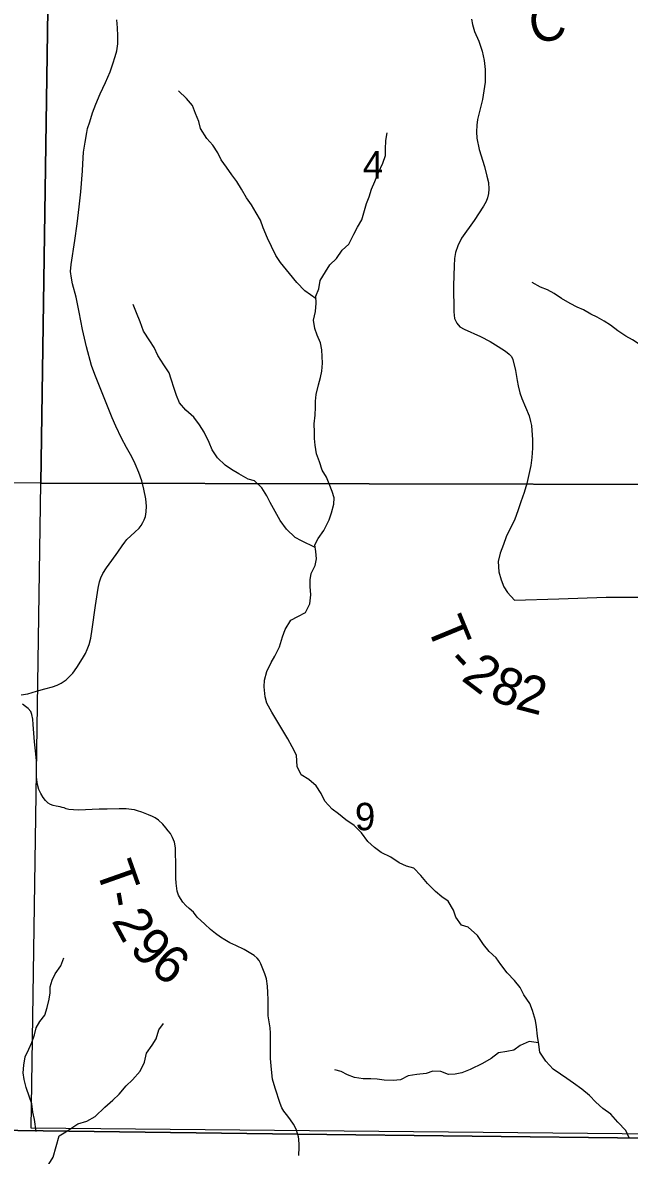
# Model space of a CAD drawing. Extents: x 0 to 34, y 0 to 22.
# Drawn here: x 6.729 to 7.655, y 16.596 to 18.326 of the extents above; entities that cross this region are included whole.
import ezdxf

# ---------------------------------------------------------------- set-up
doc = ezdxf.new("R2010")
doc.units = 0
for name, color, linetype in [('GM_X_County_Road', 7, 'Continuous'), ('GM_X_County_Road_Text', 7, 'Continuous'), ('GM_X_Minor_River', 7, 'Continuous'), ('GM_X_Rail_Line', 7, 'Continuous'), ('GM_X_Section', 7, 'Continuous'), ('GM_X_Section_Text', 7, 'Continuous'), ('GM_X_Township_Road', 7, 'Continuous'), ('GM_X_Township_Road_Text', 7, 'Continuous'), ('SH_Cut_Line', 7, 'Continuous')]:
    doc.layers.add(name, color=color, linetype=linetype)

msp = doc.modelspace()

# ---------------------------------------------------------------- linework, layer by layer
at = {"layer": 'GM_X_County_Road'}
msp.add_lwpolyline([(6.7266, 17.2991), (6.7365, 17.3011), (6.7502, 17.3047), (6.7629, 17.3083), (6.7745, 17.3115), (6.7815, 17.314), (6.7877, 17.3171), (6.7954, 17.3225), (6.7997, 17.3267), (6.8053, 17.3322), (6.8117, 17.3409), (6.8204, 17.3548), (6.8248, 17.3623), (6.8276, 17.3687), (6.8303, 17.3762), (6.8329, 17.3859), (6.835, 17.3998), (6.8402, 17.4358), (6.8442, 17.4625), (6.8462, 17.472), (6.848, 17.4782), (6.8511, 17.4846), (6.8569, 17.4934), (6.8649, 17.5043), (6.8741, 17.517), (6.8807, 17.5269), (6.8849, 17.5325), (6.8881, 17.5368), (6.9003, 17.548), (6.9067, 17.554), (6.9099, 17.5581), (6.9123, 17.5628), (6.9143, 17.5666), (6.9163, 17.5718), (6.9177, 17.5791), (6.918, 17.5874), (6.9167, 17.5989), (6.9138, 17.6136), (6.9108, 17.6261), (6.9063, 17.639), (6.9009, 17.6524), (6.8955, 17.663), (6.8875, 17.6772), (6.8798, 17.6913), (6.871, 17.7098), (6.8653, 17.7226), (6.8531, 17.7531), (6.8471, 17.7685), (6.8391, 17.7887), (6.8341, 17.8024), (6.8264, 17.8308), (6.8202, 17.8574), (6.8153, 17.8836), (6.8103, 17.9068), (6.8052, 17.9273), (6.8034, 17.9357), (6.8019, 17.9461), (6.803, 17.9568), (6.8085, 17.9934), (6.8122, 18.0185), (6.8151, 18.0448), (6.8178, 18.0678), (6.8204, 18.0999), (6.8206, 18.1104), (6.8218, 18.128), (6.8241, 18.1433), (6.8268, 18.1584), (6.828, 18.1645), (6.8312, 18.1744), (6.8356, 18.1883), (6.8404, 18.2016), (6.8472, 18.2171), (6.8555, 18.2348), (6.8623, 18.2509), (6.8666, 18.2632), (6.8701, 18.2741), (6.8725, 18.2828), (6.8742, 18.2939), (6.8741, 18.3057), (6.8735, 18.3182), (6.8728, 18.3303)], dxfattribs=at)
at = {"layer": 'GM_X_Minor_River'}
for points in [[(7.1769, 17.904), (7.1596, 17.9163), (7.1477, 17.9291), (7.1362, 17.943), (7.1228, 17.9597), (7.1156, 17.9706), (7.109, 17.9842), (7.1028, 17.9971), (7.0959, 18.0126), (7.092, 18.0243), (7.0855, 18.0356), (7.0782, 18.0477), (7.0705, 18.0587), (7.0629, 18.0719), (7.056, 18.0836), (7.0483, 18.0938), (7.0399, 18.1055), (7.0318, 18.1165), (7.0268, 18.1274), (7.0195, 18.1388), (7.0103, 18.149), (7.0004, 18.1644), (6.998, 18.175), (6.993, 18.1875), (6.9884, 18.1993), (6.9792, 18.2102), (6.967, 18.2219)], [(7.1753, 17.7267), (7.1763, 17.7385), (7.1763, 17.748), (7.1769, 17.7582), (7.1806, 17.7727), (7.1836, 17.7841), (7.1858, 17.7935), (7.1869, 17.8057), (7.1861, 17.8163), (7.1856, 17.8262), (7.1836, 17.8368), (7.1786, 17.8489), (7.1748, 17.8591), (7.1728, 17.8716), (7.1761, 17.8849), (7.1772, 17.8978), (7.1767, 17.9084), (7.1812, 17.9194), (7.1834, 17.932), (7.1913, 17.9453), (7.1977, 17.956), (7.2082, 17.9659), (7.2169, 17.9785), (7.2267, 17.9876), (7.2346, 18.0029), (7.2402, 18.0135), (7.2466, 18.0246), (7.2507, 18.039), (7.254, 18.05), (7.2581, 18.0599), (7.2618, 18.0717), (7.2667, 18.0835), (7.2723, 18.0972), (7.279, 18.1112), (7.2828, 18.123), (7.2827, 18.1329), (7.2837, 18.1462), (7.2856, 18.1579)], [(7.7613, 17.7616), (7.7464, 17.7741), (7.7353, 17.7869), (7.7215, 17.7997), (7.7074, 17.8098), (7.6967, 17.817), (7.6834, 17.826), (7.6704, 17.835), (7.6601, 17.8414), (7.6502, 17.8474), (7.638, 17.8553), (7.6266, 17.8639), (7.617, 17.8699), (7.6064, 17.8763), (7.5965, 17.8808), (7.5854, 17.8872), (7.5759, 17.8913), (7.5648, 17.8969), (7.5519, 17.9048), (7.5404, 17.9123), (7.5305, 17.9179), (7.5199, 17.922), (7.5069, 17.9291)], [(7.1757, 17.5244), (7.1549, 17.5347), (7.145, 17.5395), (7.1316, 17.5523), (7.122, 17.5656), (7.1143, 17.5795), (7.107, 17.5932), (7.1016, 17.6034), (7.094, 17.6154), (7.0829, 17.626), (7.073, 17.629), (7.0589, 17.6368), (7.0478, 17.6436), (7.0379, 17.65), (7.0265, 17.6613), (7.018, 17.6734), (7.0138, 17.6847), (7.0061, 17.7006), (6.9988, 17.7115), (6.99, 17.7232), (6.9781, 17.7342), (6.9686, 17.7455), (6.9636, 17.7565), (6.9601, 17.7671), (6.9558, 17.7814), (6.9527, 17.7913), (6.9443, 17.8034), (6.9354, 17.8177), (6.9297, 17.8298), (6.9228, 17.84), (6.9132, 17.8547), (6.9081, 17.8691), (6.9027, 17.8827), (6.8977, 17.8956)], [(7.6552, 16.6226), (7.6502, 16.6341), (7.638, 16.6465), (7.6273, 16.6589), (7.6147, 16.6676), (7.604, 16.677), (7.5945, 16.6876), (7.583, 16.697), (7.57, 16.706), (7.5601, 16.7131), (7.5502, 16.7199), (7.5388, 16.7278), (7.528, 16.7398), (7.5188, 16.7538), (7.5169, 16.7652), (7.5153, 16.7781), (7.5133, 16.7925), (7.5121, 16.8019), (7.5074, 16.8171), (7.5032, 16.8277), (7.494, 16.8409), (7.4886, 16.8522), (7.4798, 16.8632), (7.4687, 16.8745), (7.4591, 16.8877), (7.4518, 16.8975), (7.4415, 16.9073), (7.4327, 16.9179), (7.4235, 16.9318), (7.4094, 16.9446), (7.3991, 16.9476), (7.3903, 16.9597), (7.3868, 16.9703), (7.3787, 16.9843), (7.3692, 16.9907), (7.3593, 16.9989), (7.347, 17.0114), (7.3367, 17.0234), (7.326, 17.0344), (7.315, 17.0377), (7.3039, 17.0426), (7.291, 17.0512), (7.2765, 17.0587), (7.2662, 17.0662), (7.2562, 17.0753), (7.2463, 17.0885), (7.2352, 17.0998), (7.2226, 17.1084), (7.2112, 17.1174), (7.2016, 17.1246), (7.1905, 17.1367), (7.1848, 17.1484), (7.1771, 17.1601), (7.166, 17.1699), (7.1542, 17.177), (7.148, 17.1899), (7.1468, 17.2073), (7.1406, 17.2198), (7.1337, 17.2319), (7.1264, 17.2447), (7.1168, 17.2602), (7.1095, 17.273), (7.1018, 17.2867), (7.0991, 17.2965), (7.0979, 17.3117), (7.0982, 17.3219), (7.1019, 17.3348), (7.1083, 17.3489), (7.1139, 17.3584), (7.121, 17.3725), (7.1258, 17.3877), (7.1299, 17.3991), (7.1386, 17.4132), (7.1492, 17.419), (7.1609, 17.4251), (7.1673, 17.4384), (7.1687, 17.4521), (7.1679, 17.4646), (7.1678, 17.4752), (7.1696, 17.4847), (7.1756, 17.4969), (7.1778, 17.5071), (7.1766, 17.5181), (7.175, 17.5287), (7.1803, 17.5383), (7.1889, 17.5504), (7.1968, 17.5668), (7.2005, 17.5771), (7.2039, 17.5904), (7.2046, 17.6002), (7.2015, 17.6101), (7.1968, 17.6214), (7.1926, 17.6316), (7.1861, 17.6426), (7.1822, 17.6551), (7.1775, 17.6672), (7.1756, 17.6805), (7.1747, 17.6911), (7.1743, 17.7005), (7.1738, 17.7134), (7.1753, 17.7267)], [(6.7496, 16.6324), (6.7468, 16.6509), (6.7445, 16.6619), (6.7429, 16.6748), (6.7394, 16.6846), (6.7344, 16.6994), (6.7312, 16.7119), (6.7296, 16.7221), (6.7307, 16.7339), (6.7329, 16.7464), (6.7381, 16.7582), (6.7426, 16.7681), (6.7471, 16.7799), (6.7497, 16.7909), (6.7553, 16.8004), (6.7625, 16.8103), (6.7662, 16.8217), (6.7692, 16.8347), (6.7706, 16.8441), (6.7709, 16.8536), (6.7739, 16.8635), (6.7784, 16.8734), (6.787, 16.8852), (6.7919, 16.8978)], [(6.7948, 16.6319), (6.8133, 16.6442), (6.827, 16.6484), (6.8394, 16.6553), (6.8542, 16.6695), (6.8666, 16.6802), (6.8764, 16.6893), (6.887, 16.7019), (6.8968, 16.7115), (6.9081, 16.7244), (6.9148, 16.7381), (6.9178, 16.7518), (6.9268, 16.7644), (6.9328, 16.7739), (6.9369, 16.7876), (6.9437, 16.7971)], [(7.5165, 16.7678), (7.5024, 16.77), (7.4888, 16.7635), (7.4789, 16.7566), (7.4683, 16.7546), (7.4554, 16.7523), (7.4441, 16.7438), (7.4312, 16.7362), (7.4123, 16.7273), (7.3994, 16.7219), (7.3892, 16.72), (7.3793, 16.7195), (7.3675, 16.724), (7.355, 16.7247), (7.3448, 16.7212), (7.3307, 16.7196), (7.3175, 16.7172), (7.3057, 16.7115), (7.2947, 16.7103), (7.2807, 16.7109), (7.2704, 16.7124), (7.2605, 16.7127), (7.2488, 16.7126), (7.2358, 16.7148), (7.2248, 16.7189), (7.2153, 16.7238), (7.2054, 16.7264)], [(6.7621, 16.5699), (6.769, 16.5824), (6.7752, 16.5933), (6.7845, 16.6258), (6.7948, 16.6319)]]:
    msp.add_lwpolyline(points, dxfattribs=at)
at = {"layer": 'GM_X_Rail_Line'}
for points in [[(5.9824, 16.6436), (7.149, 16.6283), (7.6814, 16.6224), (7.7376, 16.622), (7.7377, 16.1663), (7.7446, 16.1373), (7.7538, 15.9954), (7.756, 15.9342), (7.7526, 15.9181), (7.7434, 15.892), (7.7355, 15.6105), (7.8392, 15.6096), (8.369, 15.6108), (8.7708, 15.6025), (8.77, 15.1835), (8.767, 14.6265), (8.9, 14.624), (8.9, 20.9)], [(4.5781, 14.1), (8.76, 14.1), (8.766, 14.6043), (8.767, 14.6265), (8.77, 15.1835), (8.7708, 15.6025), (8.369, 15.6108), (7.8392, 15.6096), (7.7355, 15.6105), (7.7434, 15.892), (7.7526, 15.9181), (7.756, 15.9342), (7.7538, 15.9954), (7.7446, 16.1373), (7.7377, 16.1663), (7.7376, 16.622), (7.6814, 16.6224), (7.149, 16.6283), (5.9824, 16.6436)]]:
    msp.add_lwpolyline(points, dxfattribs=at)
at = {"layer": 'GM_X_Section'}
for points in [[(5.7885, 18.6247), (6.7712, 18.6214), (6.7568, 17.6224), (5.685, 17.6333), (5.7131, 18.626)], [(6.7712, 18.6214), (6.7897, 18.6209), (7.7667, 18.6191), (7.7595, 17.6205), (6.7568, 17.6224)], [(7.7595, 17.6205), (7.7506, 16.628), (6.7418, 16.6375), (6.7568, 17.6224)]]:
    msp.add_lwpolyline(points, close=True, dxfattribs=at)
at = {"layer": 'GM_X_Township_Road'}
for points in [[(7.4144, 18.3316), (7.4156, 18.3232), (7.419, 18.3123), (7.4253, 18.2977), (7.4305, 18.2827), (7.4336, 18.2681), (7.435, 18.2547), (7.435, 18.2353), (7.431, 18.2087), (7.4264, 18.1902), (7.4236, 18.1783), (7.4225, 18.1693), (7.4217, 18.1592), (7.4224, 18.1497), (7.4262, 18.1325), (7.4339, 18.1064), (7.4379, 18.0915), (7.4402, 18.082), (7.4408, 18.0715), (7.4402, 18.0652), (7.4387, 18.0584), (7.4365, 18.0527), (7.4328, 18.0455), (7.4182, 18.0238), (7.399, 17.9967), (7.3933, 17.9851), (7.3899, 17.9751), (7.3882, 17.966), (7.3877, 17.9545), (7.3869, 17.9244), (7.3871, 17.8841), (7.3883, 17.8739), (7.3919, 17.867), (7.3966, 17.8612), (7.403, 17.8581), (7.4282, 17.8468), (7.443, 17.8391), (7.4552, 17.8316), (7.4664, 17.8245), (7.4719, 17.8199), (7.4756, 17.816), (7.4776, 17.8117), (7.4813, 17.7949), (7.4839, 17.7792), (7.4856, 17.7714), (7.488, 17.7605), (7.4913, 17.7521), (7.5021, 17.7255), (7.5046, 17.7169), (7.5057, 17.7109), (7.5063, 17.7033), (7.5072, 17.6895), (7.5074, 17.6762), (7.5064, 17.6618), (7.5049, 17.6494), (7.4989, 17.6219), (7.4949, 17.6082), (7.4898, 17.594), (7.4852, 17.5805), (7.4804, 17.5678), (7.4673, 17.5409), (7.4629, 17.529), (7.4579, 17.5158), (7.4552, 17.5029), (7.4558, 17.487), (7.4595, 17.4748), (7.4636, 17.4642), (7.4695, 17.4554), (7.4799, 17.444), (7.5476, 17.4461), (7.6201, 17.4485), (7.6998, 17.4485)], [(6.7891, 17.1274), (6.7862, 17.1282), (6.7798, 17.1292), (6.7753, 17.1301), (6.7716, 17.1316), (6.7676, 17.1341), (6.7638, 17.1379), (6.7601, 17.1424), (6.7566, 17.1486), (6.7533, 17.1548), (6.7513, 17.1625), (6.75, 17.1734), (6.7499, 17.19), (6.7501, 17.199), (6.7482, 17.2136), (6.7469, 17.2276), (6.745, 17.2539), (6.7445, 17.2624), (6.7429, 17.2695), (6.7411, 17.2741), (6.7372, 17.2784), (6.7332, 17.2817), (6.7284, 17.2849)], [(7.1493, 16.6278), (7.1464, 16.6361), (7.1423, 16.6438), (7.138, 16.6501), (7.1337, 16.6559), (7.1277, 16.6636), (7.1247, 16.6687), (7.1219, 16.6754), (7.1144, 16.6987), (7.1104, 16.7122), (7.1086, 16.7272), (7.1072, 16.744), (7.1074, 16.7661), (7.1074, 16.7827), (7.1066, 16.7909), (7.1039, 16.8091), (7.1036, 16.8337), (7.1031, 16.8449), (7.1026, 16.8542), (7.1013, 16.8655), (7.0989, 16.8731), (7.0957, 16.881), (7.0925, 16.8885), (7.0899, 16.8936), (7.0868, 16.8972), (7.0823, 16.901), (7.0749, 16.9056), (7.0673, 16.9102), (7.0546, 16.9163), (7.0454, 16.9208), (7.0378, 16.9252), (7.0311, 16.9293), (7.0234, 16.9347), (7.0155, 16.9407), (7.0069, 16.949), (6.9953, 16.96), (6.9898, 16.9672), (6.9829, 16.973), (6.9779, 16.9778), (6.9733, 16.9829), (6.9697, 16.9882), (6.9669, 16.9932), (6.9647, 16.9995), (6.9634, 17.0117), (6.9628, 17.0193), (6.9626, 17.0339), (6.9623, 17.0658), (6.9607, 17.0745), (6.9576, 17.0814), (6.9544, 17.0874), (6.951, 17.0918), (6.9476, 17.096), (6.9427, 17.102), (6.9361, 17.1079), (6.9312, 17.1114), (6.9269, 17.1136), (6.9211, 17.1161), (6.911, 17.1201), (6.9043, 17.1223), (6.8996, 17.1236), (6.8953, 17.1242), (6.8868, 17.125), (6.8763, 17.125), (6.8579, 17.1247), (6.8456, 17.1246), (6.8142, 17.1234), (6.8063, 17.1236), (6.7992, 17.1243), (6.7953, 17.1253), (6.792, 17.1266), (6.7891, 17.1274)], [(7.1506, 16.5957), (7.1508, 16.5997), (7.1509, 16.6043), (7.151, 16.6093), (7.1509, 16.615), (7.1508, 16.6174), (7.1505, 16.6208), (7.15, 16.6244), (7.1493, 16.6278)]]:
    msp.add_lwpolyline(points, dxfattribs=at)
at = {"layer": 'SH_Cut_Line'}
for points in [[(5.9824, 16.6436), (7.149, 16.6283), (7.6814, 16.6224), (7.7376, 16.622), (7.7377, 16.1663), (7.7446, 16.1373), (7.7538, 15.9954), (7.756, 15.9342), (7.7526, 15.9181), (7.7434, 15.892), (7.7355, 15.6105), (7.8392, 15.6096), (8.369, 15.6108), (8.7708, 15.6025), (8.77, 15.1835), (8.767, 14.6265), (8.9, 14.624), (8.9, 20.9)], [(4.5781, 14.1), (8.9, 14.1), (8.9, 14.624), (8.767, 14.6265), (8.77, 15.1835), (8.7708, 15.6025), (8.369, 15.6108), (7.8392, 15.6096), (7.7355, 15.6105), (7.7434, 15.892), (7.7526, 15.9181), (7.756, 15.9342), (7.7538, 15.9954), (7.7446, 16.1373), (7.7377, 16.1663), (7.7376, 16.622), (7.6814, 16.6224), (7.149, 16.6283), (5.9824, 16.6436)]]:
    msp.add_lwpolyline(points, dxfattribs=at)

# ---------------------------------------------------------------- texts
at = {"layer": 'GM_X_County_Road_Text'}
msp.add_text('C', height=0.0568, rotation=11.1982, dxfattribs=at).set_placement((7.5083, 18.2932))
at = {"layer": 'GM_X_Section_Text'}
for s, p in [('4', (7.2483, 18.0879)), ('9', (7.2362, 17.0925))]:
    msp.add_text(s, height=0.0419, rotation=0, dxfattribs=at).set_placement(p)
at = {"layer": 'GM_X_Township_Road_Text'}
for s, rotation, p in [('T', 292.3601, (7.3451, 17.4051)), ('-', 312.8616, (7.3731, 17.3472)), ('2', 322.9202, (7.3971, 17.3228)), ('8', 338.6116, (7.4398, 17.2935)), ('2', 345.4553, (7.4794, 17.2784)), ('T', 289.469, (6.8398, 17.0339)), ('-', 279.8371, (6.8533, 16.9963)), ('2', 298.4795, (6.8639, 16.9544)), ('9', 313.9436, (6.8904, 16.9101)), ('6', 321.8, (6.921, 16.8792))]:
    msp.add_text(s, height=0.0568, rotation=rotation, dxfattribs=at).set_placement(p)

doc.saveas('drawing.dxf')
